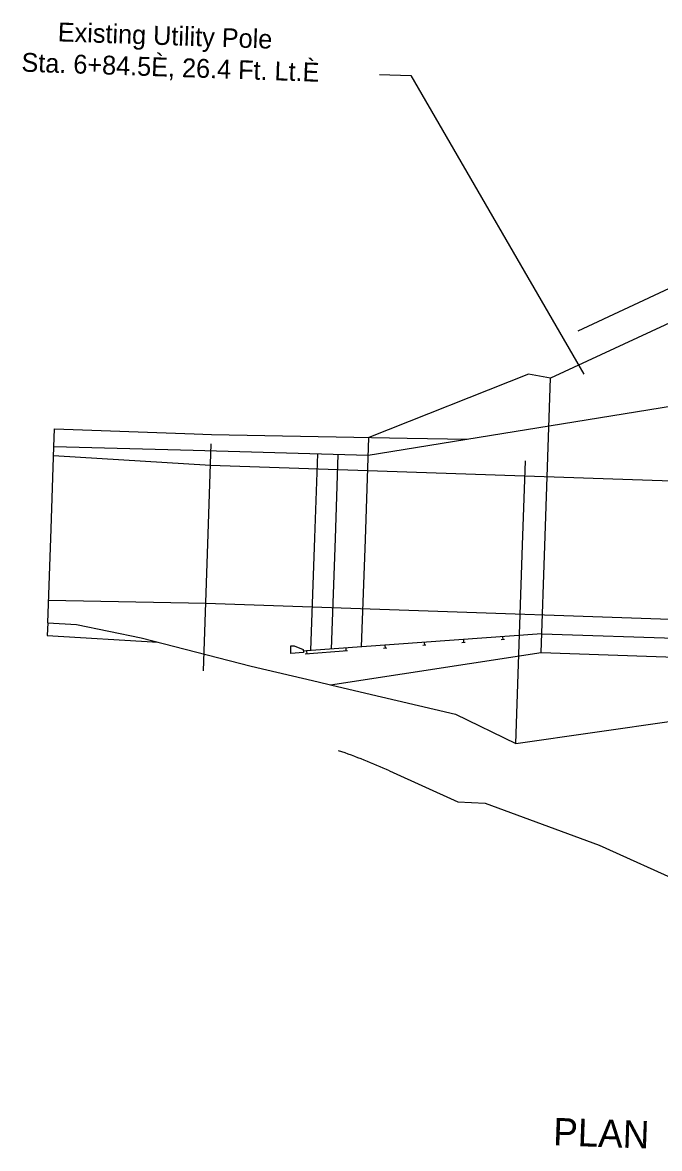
# Model space of a CAD drawing. Extents: x 2191309 to 2193046, y 863659 to 865133.
# Drawn here: x 2192468.5 to 2192569.8, y 863837.7 to 864016.7 of the extents above; entities that cross this region are included whole.
import ezdxf

# ---------------------------------------------------------------- set-up
doc = ezdxf.new("R2010")
doc.units = 0
for name, color, linetype in [('ANNOTATION', 7, 'Continuous'), ('D_Guardrail_Beam_Rt', 7, 'Continuous'), ('D_Guardrail_End_MidSplice', 7, 'Continuous'), ('D_Roadway_Drive_Gravel', 7, 'Continuous'), ('D_Roadway_Edge_Shoulder', 7, 'Continuous'), ('D_Roadway_Edge_TW', 7, 'Continuous'), ('D_Slope_ClearingLimitLine', 7, 'Continuous'), ('D_Slope_Toe', 7, 'Continuous'), ('DIMENSIONS', 7, 'Continuous'), ('H_V CONTROLS', 7, 'Continuous'), ('JUNK', 7, 'Continuous')]:
    doc.layers.add(name, color=color, linetype=linetype)

msp = doc.modelspace()

# ---------------------------------------------------------------- linework, layer by layer
at = {"layer": 'D_Guardrail_Beam_Rt'}
msp.add_line((2192551.07, 863919.54), (2192622.91, 863917.08), dxfattribs=at)
at = {"layer": 'D_Guardrail_End_MidSplice'}
for p, q in [((2192551.07, 863919.54), (2192513.67, 863916.82)), ((2192544.84, 863919.09), (2192544.88, 863918.59)), ((2192511.16, 863916.39), (2192511.2, 863917.64)), ((2192511.2, 863917.64), (2192511.7, 863917.62)), ((2192511.7, 863917.62), (2192513.16, 863917.04)), ((2192513.16, 863917.04), (2192513.19, 863916.54)), ((2192519.91, 863917.28), (2192519.94, 863916.78)), ((2192526.43, 863917.25), (2192525.93, 863917.21)), ((2192526.14, 863917.73), (2192526.18, 863917.23)), ((2192532.66, 863917.7), (2192532.16, 863917.67)), ((2192532.37, 863918.18), (2192532.41, 863917.68)), ((2192538.89, 863918.15), (2192538.39, 863918.12)), ((2192538.61, 863918.64), (2192538.64, 863918.14)), ((2192545.13, 863918.61), (2192544.63, 863918.57)), ((2192513.19, 863916.54), (2192511.16, 863916.39)), ((2192513.67, 863916.82), (2192513.17, 863916.79)), ((2192520.19, 863916.8), (2192513.46, 863916.31)), ((2192513.96, 863916.34), (2192513.46, 863916.31)), ((2192513.67, 863916.82), (2192513.71, 863916.32)), ((2192520.19, 863916.8), (2192519.69, 863916.76))]:
    msp.add_line(p, q, dxfattribs=at)
at = {"layer": 'D_Roadway_Drive_Gravel'}
for points in [[(2192473.5, 863949.27), (2192473.5, 863949.27), (2192473.6, 863952.14), (2192495.83, 863951.3), (2192498.59, 863951.24), (2192529.67, 863950.65), (2192539.31, 863950.46)], [(2192472.54, 863921.29), (2192472.47, 863919.24), (2192490.11, 863918.18)]]:
    msp.add_lwpolyline(points, dxfattribs=at)
at = {"layer": 'D_Roadway_Edge_Shoulder'}
for p, q in [((2192577.58, 863956.65), (2192523.49, 863947.9)), ((2192473.06, 863936.23), (2192473.5, 863949.27)), ((2192472.54, 863921.29), (2192473.06, 863936.23)), ((2192517.47, 863911.44), (2192550.97, 863916.54)), ((2192550.97, 863916.54), (2192651.87, 863913.08))]:
    msp.add_line(p, q, dxfattribs=at)
for points in [[(2192523.49, 863947.9), (2192495.66, 863948.68), (2192473.5, 863949.27)], [(2192472.54, 863921.29), (2192477.13, 863921.03), (2192487.38, 863918.88), (2192504.87, 863914.4), (2192515.55, 863911.89), (2192517.47, 863911.44)]]:
    msp.add_lwpolyline(points, dxfattribs=at)
at = {"layer": 'D_Roadway_Edge_TW'}
for points in [[(2192473.46, 863947.87), (2192498.42, 863946.36), (2192602.97, 863942.78), (2192652.94, 863944.4)], [(2192472.67, 863924.87), (2192497.66, 863924.38), (2192602.21, 863920.79), (2192651.96, 863915.75)]]:
    msp.add_lwpolyline(points, dxfattribs=at)
at = {"layer": 'D_Slope_ClearingLimitLine'}
for p, q in [((2192526.86, 863897.74), (2192537.71, 863892.83)), ((2192560.18, 863885.95), (2192577.66, 863878.03))]:
    msp.add_line(p, q, dxfattribs=at)
for points in [[(2192556.84, 863967.72), (2192572.18, 863974.83)], [(2192537.71, 863892.83), (2192542.06, 863892.58), (2192560.18, 863885.95)]]:
    msp.add_lwpolyline(points, dxfattribs=at)
msp.add_arc((2192489.53, 863815.3), 90.5, 65.6364, 71.1468, dxfattribs=at)
at = {"layer": 'D_Slope_Toe'}
for points in [[(2192574.28, 863970.29), (2192552.47, 863960.18), (2192548.95, 863960.83), (2192523.58, 863950.76)], [(2192517.47, 863911.44), (2192522.2, 863910.33), (2192537.38, 863906.76), (2192546.93, 863902.11), (2192572.07, 863905.71), (2192575.35, 863906.18), (2192575.84, 863906.15), (2192597.13, 863906.95), (2192613.89, 863907.09), (2192622.14, 863906.86), (2192627.35, 863907.02), (2192628.72, 863906.01), (2192630.64, 863904.93), (2192635.83, 863902.28)]]:
    msp.add_lwpolyline(points, dxfattribs=at)
at = {"layer": 'DIMENSIONS'}
msp.add_lwpolyline([(2192525.27, 864008.46), (2192530.26, 864008.29), (2192557.74, 863960.81)], dxfattribs=at)
at = {"layer": 'JUNK'}
for p, q in [((2192551.55, 863933.53), (2192552.47, 863960.18)), ((2192498.04, 863935.37), (2192498.53, 863949.73)), ((2192523.03, 863934.51), (2192523.58, 863950.76)), ((2192514.99, 863934.79), (2192515.45, 863948.13)), ((2192518.27, 863934.68), (2192518.72, 863948.03)), ((2192548.01, 863933.65), (2192548.47, 863947.01)), ((2192497.3, 863913.67), (2192498.04, 863935.37)), ((2192514.38, 863916.87), (2192514.99, 863934.79)), ((2192517.66, 863917.11), (2192518.27, 863934.68)), ((2192522.44, 863917.46), (2192523.03, 863934.51)), ((2192546.93, 863902.11), (2192548.01, 863933.65)), ((2192550.97, 863916.54), (2192551.55, 863933.53))]:
    msp.add_line(p, q, dxfattribs=at)

# ---------------------------------------------------------------- texts
at = {"layer": 'ANNOTATION'}
for s, p in [('Existing Utility Pole', (2192474.1, 864013.73)), ('Sta. 6+84.5È, 26.4 Ft. Lt.È', (2192468.32, 864008.92))]:
    msp.add_text(s, height=3, rotation=358.0343, dxfattribs=at).set_placement(p)
at = {"layer": 'H_V CONTROLS'}
msp.add_text('PLAN', height=4.375, rotation=358.0343, dxfattribs=at).set_placement((2192552.84, 863838.21))

doc.saveas('drawing.dxf')
